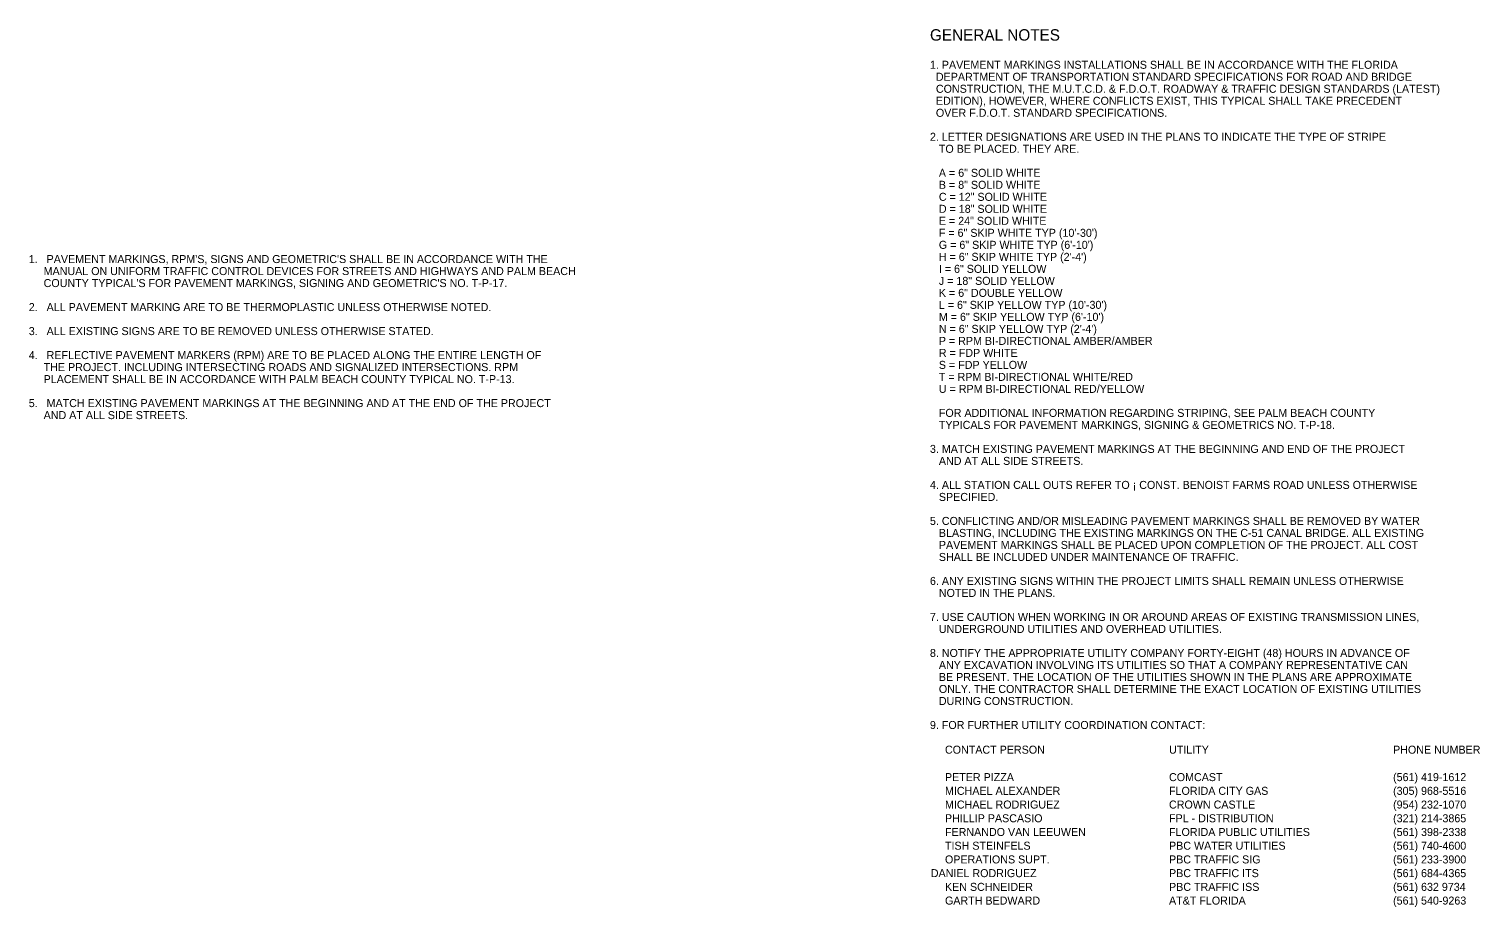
# Model space of a CAD drawing. Extents: x -285 to 540, y -16 to 370.
import ezdxf

# ---------------------------------------------------------------- set-up
doc = ezdxf.new("R2010")
doc.units = 0
doc.layers.add('TextMisc', color=7, linetype='Continuous')

msp = doc.modelspace()

# ---------------------------------------------------------------- texts
at = {"layer": 'TextMisc'}
for s, height, p in [('GENERAL NOTES', 4, (30.19, 365.95)), ('1. PAVEMENT MARKINGS INSTALLATIONS SHALL BE IN ACCORDANCE WITH THE FLORIDA', 2.8, (30.17, 356.1)), ('  CONSTRUCTION, THE M.U.T.C.D. & F.D.O.T. ROADWAY & TRAFFIC DESIGN STANDARDS (LATEST)', 2.8, (30.17, 347.7)), ('  DEPARTMENT OF TRANSPORTATION STANDARD SPECIFICATIONS FOR ROAD AND BRIDGE', 2.8, (30.17, 351.9)), ('  EDITION), HOWEVER, WHERE CONFLICTS EXIST, THIS TYPICAL SHALL TAKE PRECEDENT  ', 2.8, (30.17, 343.5)), ('  OVER F.D.O.T. STANDARD SPECIFICATIONS. ', 2.8, (30.17, 339.3)), ('2. LETTER DESIGNATIONS ARE USED IN THE PLANS TO INDICATE THE TYPE OF STRIPE', 2.8, (30.17, 330.9)), ('   TO BE PLACED. THEY ARE.', 2.8, (30.17, 326.7)), ('   A = 6" SOLID WHITE', 2.8, (30.17, 318.3)), ('   B = 8" SOLID WHITE', 2.8, (30.17, 314.1)), ('   C = 12" SOLID WHITE', 2.8, (30.17, 309.9)), ('   D = 18" SOLID WHITE', 2.8, (30.17, 305.7)), ('   E = 24" SOLID WHITE', 2.8, (30.17, 301.5)), ('   F = 6" SKIP WHITE TYP (10\'-30\')', 2.8, (30.17, 297.3)), ('   G = 6" SKIP WHITE TYP (6\'-10\')', 2.8, (30.17, 293.1)), ("1.   PAVEMENT MARKINGS, RPM'S, SIGNS AND GEOMETRIC'S SHALL BE IN ACCORDANCE WITH THE", 2.8, (-285.17, 288.12)), ('   H = 6" SKIP WHITE TYP (2\'-4\')', 2.8, (30.17, 288.9)), ('     MANUAL ON UNIFORM TRAFFIC CONTROL DEVICES FOR STREETS AND HIGHWAYS AND PALM BEACH', 2.8, (-285.17, 283.92)), ('   I = 6" SOLID YELLOW', 2.8, (30.17, 284.7)), ("     COUNTY TYPICAL'S FOR PAVEMENT MARKINGS, SIGNING AND GEOMETRIC'S NO. T-P-17.", 2.8, (-285.17, 279.72)), ('   J = 18" SOLID YELLOW', 2.8, (30.17, 280.5)), ('   K = 6" DOUBLE YELLOW', 2.8, (30.17, 276.3)), ('   L = 6" SKIP YELLOW TYP (10\'-30\')', 2.8, (30.17, 272.1)), ('2.   ALL PAVEMENT MARKING ARE TO BE THERMOPLASTIC UNLESS OTHERWISE NOTED.', 2.8, (-285.17, 271.32)), ('   M = 6" SKIP YELLOW TYP (6\'-10\')', 2.8, (30.17, 267.9)), ('3.   ALL EXISTING SIGNS ARE TO BE REMOVED UNLESS OTHERWISE STATED.', 2.8, (-285.17, 262.92)), ('   N = 6" SKIP YELLOW TYP (2\'-4\')', 2.8, (30.17, 263.7)), ('   P = RPM BI-DIRECTIONAL AMBER/AMBER', 2.8, (30.17, 259.5)), ('4.   REFLECTIVE PAVEMENT MARKERS (RPM) ARE TO BE PLACED ALONG THE ENTIRE LENGTH OF', 2.8, (-285.17, 254.52)), ('   S = FDP YELLOW', 2.8, (30.17, 251.1)), ('   R = FDP WHITE', 2.8, (30.17, 255.3)), ('     THE PROJECT. INCLUDING INTERSECTING ROADS AND SIGNALIZED INTERSECTIONS. RPM', 2.8, (-285.17, 250.32)), ('     PLACEMENT SHALL BE IN ACCORDANCE WITH PALM BEACH COUNTY TYPICAL NO. T-P-13.', 2.8, (-285.17, 246.12)), ('   T = RPM BI-DIRECTIONAL WHITE/RED', 2.8, (30.17, 246.9)), ('   U = RPM BI-DIRECTIONAL RED/YELLOW', 2.8, (30.17, 242.7)), ('5.   MATCH EXISTING PAVEMENT MARKINGS AT THE BEGINNING AND AT THE END OF THE PROJECT', 2.8, (-285.17, 237.72)), ('     AND AT ALL SIDE STREETS.', 2.8, (-285.17, 233.52)), ('   FOR ADDITIONAL INFORMATION REGARDING STRIPING, SEE PALM BEACH COUNTY', 2.8, (30.17, 234.3)), ('   TYPICALS FOR PAVEMENT MARKINGS, SIGNING & GEOMETRICS NO. T-P-18.', 2.8, (30.17, 230.1)), ('3. MATCH EXISTING PAVEMENT MARKINGS AT THE BEGINNING AND END OF THE PROJECT', 2.8, (30.17, 221.7)), ('   AND AT ALL SIDE STREETS.', 2.8, (30.17, 217.5)), ('4. ALL STATION CALL OUTS REFER TO ¡ CONST. BENOIST FARMS ROAD UNLESS OTHERWISE', 2.8, (30.17, 209.1)), ('   SPECIFIED.', 2.8, (30.17, 204.9)), ('5. CONFLICTING AND/OR MISLEADING PAVEMENT MARKINGS SHALL BE REMOVED BY WATER', 2.8, (30.17, 196.5)), ('   BLASTING, INCLUDING THE EXISTING MARKINGS ON THE C-51 CANAL BRIDGE. ALL EXISTING ', 2.8, (30.17, 192.3)), ('   PAVEMENT MARKINGS SHALL BE PLACED UPON COMPLETION OF THE PROJECT. ALL COST ', 2.8, (30.17, 188.1)), ('   SHALL BE INCLUDED UNDER MAINTENANCE OF TRAFFIC.', 2.8, (30.17, 183.9)), ('6. ANY EXISTING SIGNS WITHIN THE PROJECT LIMITS SHALL REMAIN UNLESS OTHERWISE', 2.8, (30.17, 175.5)), ('   NOTED IN THE PLANS.', 2.8, (30.17, 171.3)), ('7. USE CAUTION WHEN WORKING IN OR AROUND AREAS OF EXISTING TRANSMISSION LINES,', 2.8, (30.17, 162.9)), ('   UNDERGROUND UTILITIES AND OVERHEAD UTILITIES.', 2.8, (30.17, 158.7)), ('8. NOTIFY THE APPROPRIATE UTILITY COMPANY FORTY-EIGHT (48) HOURS IN ADVANCE OF ', 2.8, (30.17, 150.3)), ('   ANY EXCAVATION INVOLVING ITS UTILITIES SO THAT A COMPANY REPRESENTATIVE CAN', 2.8, (30.17, 146.1)), ('   BE PRESENT. THE LOCATION OF THE UTILITIES SHOWN IN THE PLANS ARE APPROXIMATE', 2.8, (30.17, 141.9)), ('   ONLY. THE CONTRACTOR SHALL DETERMINE THE EXACT LOCATION OF EXISTING UTILITIES', 2.8, (30.17, 137.7)), ('   DURING CONSTRUCTION.', 2.8, (30.17, 133.5)), ('9. FOR FURTHER UTILITY COORDINATION CONTACT:', 2.8, (30.17, 125.1)), ('CONTACT PERSON', 2.8, (35.43, 116.46)), ('UTILITY', 2.8, (113.83, 116.46)), ('PHONE NUMBER', 2.8, (192.23, 116.46)), ('PETER PIZZA', 2.8, (35.43, 106.86)), ('COMCAST', 2.8, (113.83, 106.86)), ('(561) 419-1612', 2.8, (192.23, 106.86)), ('MICHAEL ALEXANDER', 2.8, (35.43, 102.06)), ('FLORIDA CITY GAS', 2.8, (113.83, 102.06)), ('(305) 968-5516', 2.8, (192.23, 102.06)), ('MICHAEL RODRIGUEZ', 2.8, (35.43, 97.26)), ('CROWN CASTLE', 2.8, (113.83, 97.26)), ('(954) 232-1070', 2.8, (192.23, 97.26)), ('PHILLIP PASCASIO', 2.8, (35.43, 92.46)), ('FPL - DISTRIBUTION', 2.8, (113.83, 92.46)), ('(321) 214-3865', 2.8, (192.23, 92.46)), ('FERNANDO VAN LEEUWEN', 2.8, (35.43, 87.66)), ('FLORIDA PUBLIC UTILITIES', 2.8, (113.83, 87.66)), ('(561) 398-2338', 2.8, (192.23, 87.66)), ('TISH STEINFELS', 2.8, (35.43, 82.86)), ('PBC WATER UTILITIES', 2.8, (113.83, 82.86)), ('(561) 740-4600', 2.8, (192.23, 82.86)), ('OPERATIONS SUPT. ', 2.8, (35.43, 78.06)), ('PBC TRAFFIC SIG               ', 2.8, (113.83, 78.06)), ('(561) 233-3900', 2.8, (192.23, 78.06)), ('(561) 684-4365', 2.8, (192.23, 73.26)), ('      DANIEL RODRIGUEZ', 2.8, (24.23, 73.26)), ('KEN SCHNEIDER', 2.8, (35.43, 68.46)), ('PBC TRAFFIC ITS', 2.8, (113.83, 73.26)), ('PBC TRAFFIC ISS               ', 2.8, (113.83, 68.46)), ('(561) 632 9734', 2.8, (192.23, 68.46)), ('GARTH BEDWARD', 2.8, (35.43, 63.66)), ('AT&T FLORIDA', 2.8, (113.83, 63.66)), ('(561) 540-9263', 2.8, (192.23, 63.66))]:
    msp.add_text(s, height=height, dxfattribs=at).set_placement(p)

doc.saveas('drawing.dxf')
